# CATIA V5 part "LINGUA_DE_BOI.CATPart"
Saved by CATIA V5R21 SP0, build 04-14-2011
Part number: Part1
Material "Grey Blue": density 7860 kg/m3, Young's modulus 2e+11 Pa, Poisson ratio 0.266
Bounding box of the stored display mesh (mm): x -150 to 150, y -300 to 300, z 0.421 to 159.947
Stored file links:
  C:\Users\rodri\OneDrive\Área de Trabalho\FACULDADE\3°semestre\Sistemas Aeroespaciais\Projeto de avião 2019-02\CAD\LINGUA_DE_BOI.CATPart
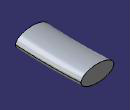
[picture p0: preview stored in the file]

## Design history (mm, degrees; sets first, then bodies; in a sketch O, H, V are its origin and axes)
Body1 (main body), material "Grey Blue"
  Sketch1 on yz-plane, origin (0, 0, 0), H (0, 1, 0), V (0, 0, 1)
    point P1 (-300, 160)
    line L1 (-300, 160) -> (-300, 10)
    arc A1 centre (0, 4505) radius 4505 from (-300, 10) to (300, 10) ccw
    line L2 (300, 10) -> (300, 160)
    arc A2 centre (0, 4655) radius 4505 from (300, 160) to (-300, 160) cw
    point P7 (0, 150)
    length L1 = 150
    length L2 = 150
    distance L1 L2 = 600
    distance A2 A1 = 150
    distance P1 H = 160
    vertical: L1 V, L2 V
    coincidence: A1 O, A2 P7, P7 V
    symmetry: L2 L1 V
    tangency: A1 H
  Pad1: profile Sketch1, direction (1, 0, 0), length 150, mirrored extent
  Sketch2 on face of Pad1 from Sketch1.L1, origin (0, -300, 0), H (1, 0, 0), V (0, 0, 1)
    point P1 (0, 85)
    ellipse A1 centre (0, 85) semi-axes 150, 75 rotation 0
    reference projected line E1 (-150, 10) -> (150, 10) from edge [face of Pad1 from Sketch1.A1 | face of Pad1 from Sketch1.L1]
    line L1 (-315.5085, 248.0164) -> (304.8358, 248.0164)
    line L2 (304.8358, 248.0164) -> (304.8358, -127.6508)
    line L3 (304.8358, -127.6508) -> (-315.5085, -127.6508)
    line L4 (-315.5085, -127.6508) -> (-315.5085, 248.0164)
    "Radius" A1 = 150
    distance P1 E1 = 75
    "Radius" A1 = 75
  Sketch3 on yz-plane, origin (0, 0, 0), H (0, 1, 0), V (0, 0, 1)
    arc A1 centre (0, 4655) radius 4580 from (-559.7604, 109.3352) to (519.2883, 104.5341) ccw
    reference projected arc E1 centre (0, 4655) radius 4505 from (-300, 160) to (300, 160) ccw from Sketch1.A2
    reference projected arc E2 centre (0, 4505) radius 4505 from (-300, 10) to (300, 10) ccw from Sketch1.A1
    reference projected arc E3 centre (0, 4655) radius 4505 from (-300, 160) to (300, 160) ccw from Sketch1.A2
    distance A1 E1 = 75
    distance A1 E2 = 75
    radius E3 = 4505 (reference)
    radius A1 = 4580
  Slot1: profile Sketch2, centre curve Sketch3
